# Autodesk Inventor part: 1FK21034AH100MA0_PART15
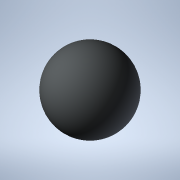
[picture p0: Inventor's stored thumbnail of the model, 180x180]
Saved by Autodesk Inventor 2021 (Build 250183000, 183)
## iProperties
Created: 2025-04
Part Number: 1FK21034AH100MA0_PART15
Material: Generic
Catalog Web Link: www.3dfindit.com
Description: -Servo synchronous motor
Document SubType Name: Modeling
Designer: psAdmin
Mass: 0.113097 g
Surface Area: 1.13097 cm^2
Volume: 0.113097 cm^3
Density: 1 g/cm^3
Appearance: PSOLRGB-212-217-219
Category: PARTsolutions
Title: 1FK21034AH100MA0_PART15
Author: Cadenas PARTsolutions
Comments: Servo synchronous motor
Sending System: PARTsolutions
Preprocessor: ST-DEVELOPER v19.3
PSOL_IDENT_0: {$CADENAS_DATA/23d-libs/siemens_ag/_cat_/39/97/1fk21034ah100ma0.prj},216 {VTYP=3D},{NB=1FK21034AH100
PSOL_IDENT_1: MA0_PART15},{LINA=1FK21034AH100MA0_PART15},{NN=1FK21034AH100MA0_PART15},{NOPRJ=TRUE},{DATE=19.08.202
PSOL_IDENT_2: 5 14:00:33},{GEOMDATE=30.07.2025 02:02:21},{VERSION=},{LINEID=10},{WBVAR=},{WBNUMERIC=}  {NB=1FK2103
PSOL_IDENT_3: 4AH100MA0_PART15},{LINA=1FK21034AH100MA0_PART15},{KT=DUMMY},{PREVIEW=../../../_pool_/d3/78/p_d211_xx
PSOL_IDENT_4: _00934j.png},{DESCSHORT=SIMOTICS S-1FK2 HD, SINAMICS S210 3AC 400V-480V, 1.01 Nm, 4500 rpm},{DESCLON
PSOL_IDENT_5: G=SIMOTICS S-1FK2 HD servo motor M0=1.27 Nm; PN = 0.48 kW at nN=4500 rpm (380-480 V); PN = 0.3 kW at
PSOL_IDENT_6: nN=2500 rpm (200-240 V); with holding brake; degree of protection IP64; cylindrical shaft D14 x 30
PSOL_IDENT_7: mm; absolute encoder 22-bit + 12-bit multiturn (encoder AM22DQC); with OCC interface; plug size M17,
PSOL_IDENT_8: rotatable; SIMOTICS S-1FK2 servomotorfor a wide range of uses in industrial environments. SIMOTICS
PSOL_IDENT_9: S‑1FK2 servomotors are compact synchronous motors with a high dynamic performance that set themselve
PSOL_IDENT_10: s apart as a result of their high power density, degree of protection and overload capability. The m
PSOL_IDENT_11: otors are available in two variants: as High Dynamic variant (highest dynamic performance as a resul
PSOL_IDENT_12: t of the low intrinsic moment of inertia for applications demanding a high dynamic performance with
PSOL_IDENT_13: low moved masses) - and as Compact variant (precise and stable closed-loop control for medium up to
PSOL_IDENT_14: large moved masses as a result of a medium intrinsic moment of inertia). SIMOTICSS‑1FK2 servomotors
PSOL_IDENT_15: fully exploit their strengths in a system with the SINAMICSS210 frequency converter and simple conne
PSOL_IDENT_16: ction using the one cable connection (OCC). Advantages include the short control and positioning tim
PSOL_IDENT_17: es, fast and precise correction of disturbing quantities as well as stable control with a high dynam
PSOL_IDENT_18: ic performance. The servo motors can be configured to address a wide range of requirements. For exam
PSOL_IDENT_19: ple with and without holding brake, IP64 or IP65 degree of protection, singleturn or multiturn absol
PSOL_IDENT_20: ute encoders - to name just a few. Further, the servomotors are available in different shaft heights
PSOL_IDENT_21: extending from 20 to 100. A shaft sealing ring is available to achieve an IP65 degree of protection
PSOL_IDENT_22: and for subsequent mounting at the motor or as spare part. SIMOTICS - the optimum motor for each an
PSOL_IDENT_23: d every motion control application.},{INTNO=195125454019},{SUPPLIERALTNO=1FK2103-4AH10-0MA0},{MANUID=
PSOL_IDENT_24: 1FK21034AH100MA0},{MANUNAME=Siemens},{MANUTYPEDESC=SYNCHRONOUS MOTOR 1FK2 HD 1,27 NM},{AAU732=SIMOTI
PSOL_IDENT_25: CS},{AAO057=S-1FK2},{AAU734=SIMOTICS S-1FK2 HD servo motor M0=1.27 Nm; PN = 0.48 kW at nN=4500 rpm (
PSOL_IDENT_26: 380-480 V); PN = 0.3 kW at nN=2500 rpm (200-240 V); with holding brake; degree of protection IP64; c
PSOL_IDENT_27: ylindrical shaft D14 x 30 mm; absolute encoder 22-bit + 12-bit multiturn (encoder AM22DQC); with OCC
PSOL_IDENT_28: interface; plug size M17, rotatable;},{AAW338=SYNCHRONOUS MOTOR 1FK2 HD 1,27 NM},{AAO742=SIMOTICS},
PSOL_IDENT_29: {AAO663=4034106444921},{NOCUPEROU=1},{PRICEQUANTITY=1},{QUANTITYMIN=1},{QUANTITYINT=1},{CTN=85015100
PSOL_IDENT_30: },{COO=RO},{AAO676=1FK2103-4AH10-0MA0},{AAO677=Siemens AG},{ORDERUNIT=C62},{CONTENTUNIT=C62}
NB: 1FK21034AH100MA0_PART15
NT: Servo synchronous motor
NBSYN: $MANUID._PART15
LINA: 1FK21034AH100MA0_PART15
CATALOG: SIEMENS
PREVIEW: ../../../_pool_/d3/78/p_d211_xx_00934j.png
DESCSHORT: SIMOTICS S-1FK2 HD, SINAMICS S210 3AC 400V-480V, 1.01 Nm, 4500 rpm
DESCLONG: SIMOTICS S-1FK2 HD servo motor M0=1.27 Nm; PN = 0.48 kW at nN=4500 rpm (380-480 V); PN = 0.3 kW at nN=2500 rpm (200-240 V); with holding brake; degree of protec
INTNO: 195125454019
SUPPLIERALTNO: 1FK2103-4AH10-0MA0
MANUID: 1FK21034AH100MA0
MANUNAME: Siemens
MANUTYPEDESC: SYNCHRONOUS MOTOR 1FK2 HD 1,27 NM
AAU732: SIMOTICS
AAO057: S-1FK2
AAU734: SIMOTICS S-1FK2 HD servo motor M0=1.27 Nm; PN = 0.48 kW at nN=4500 rpm (380-480 V); PN = 0.3 kW at nN=2500 rpm (200-240 V); with holding brake; degree of protec
AAW338: SYNCHRONOUS MOTOR 1FK2 HD 1,27 NM
AAO742: SIMOTICS
AAO663: 4034106444921.0
NOCUPEROU: 1
PRICEQUANTITY: 1
QUANTITYMIN: 1
QUANTITYINT: 1
CTN: 85015100
COO: RO
ARTICLENO: 1FK21034AH100MA0_PART15
BOMINFO: 1FK21034AH100MA0_PART15
CREATOR: CADENAS GmbH
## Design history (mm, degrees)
feature "2025_04_17_15_09_00_0361"
body "Solid1"
